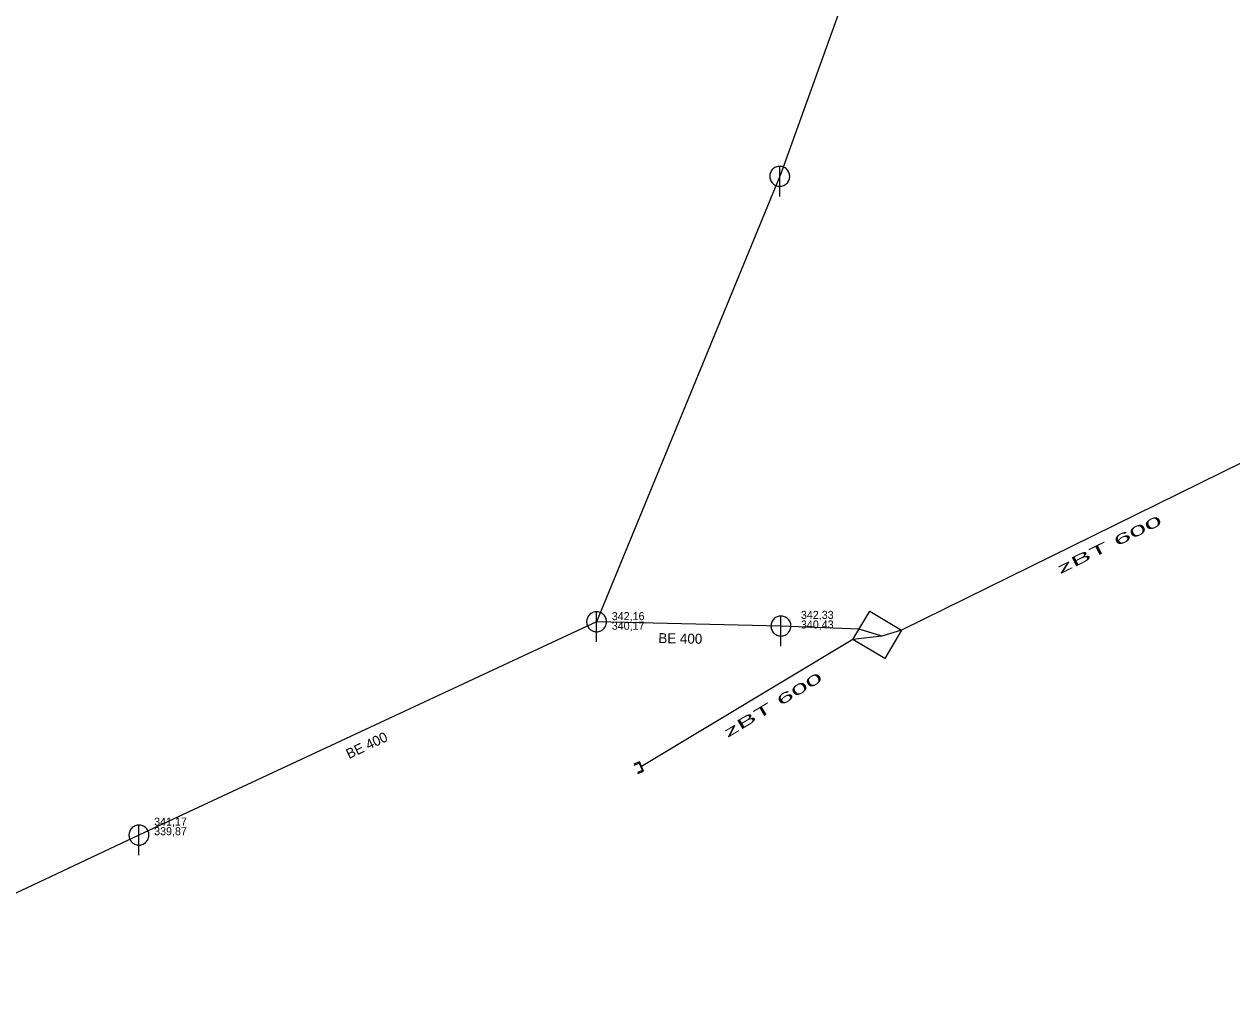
# Model space of a CAD drawing. Extents: x -724325 to -723665, y -972119 to -970722.
# Drawn here: x -724126.1 to -724005.4, y -971021.9 to -970925.2 of the extents above; entities that cross this region are included whole.
import ezdxf

# ---------------------------------------------------------------- set-up
doc = ezdxf.new("R2010")
doc.units = 0
doc.header["$LTSCALE"] = 0.4
for name, color, linetype, lineweight in [('1', 7, 'Continuous', 25), ('14', 7, 'Continuous', 25), ('22', 7, 'Continuous', 13), ('29', 7, 'Continuous', 13)]:
    doc.layers.add(name, color=color, linetype=linetype, lineweight=lineweight)
doc.layers.add('19', color=7, linetype='Continuous')

msp = doc.modelspace()

# ---------------------------------------------------------------- linework, layer by layer
at = {"layer": '1', "lineweight": 13}
msp.add_lwpolyline([(-724043.239, -970986.71), (-724041.559, -970983.87), (-724038.379, -970985.76), (-724040.059, -970988.59)], close=True, dxfattribs=at)
at = {"layer": '14'}
for p, q in [((-724032.99, -970891.76), (-724050.565, -970940.422)), ((-724050.565, -970940.421), (-724068.879, -970984.93)), ((-724114.64, -971006.25), (-724147.899, -971021.91))]:
    msp.add_line(p, q, dxfattribs=at)
for points in [[(-724002.16, -970967.949), (-724038.379, -970985.76), (-724040.368, -970986.355)], [(-724050.44, -970985.359), (-724068.879, -970984.93), (-724114.64, -971006.25)], [(-724040.368, -970986.355), (-724042.629, -970985.68), (-724050.44, -970985.359)], [(-724040.368, -970986.355), (-724043.239, -970986.71), (-724064.379, -970999.39)]]:
    msp.add_lwpolyline(points, dxfattribs=at)
at = {"layer": '22'}
for p, q in [((-724050.565, -970942.421), (-724050.564, -970939.421)), ((-724068.879, -970986.93), (-724068.878, -970983.93)), ((-724050.44, -970987.359), (-724050.439, -970984.359)), ((-724114.64, -971008.25), (-724114.639, -971005.25))]:
    msp.add_line(p, q, dxfattribs=at)
for points in [[(-724049.565, -970940.421), (-724049.57, -970940.312), (-724049.588, -970940.204), (-724049.618, -970940.098), (-724049.658, -970939.997), (-724049.71, -970939.9), (-724049.772, -970939.81), (-724049.844, -970939.727), (-724049.924, -970939.653), (-724050.012, -970939.587), (-724050.106, -970939.532), (-724050.206, -970939.487), (-724050.311, -970939.454), (-724050.418, -970939.432), (-724050.527, -970939.422), (-724050.637, -970939.424), (-724050.745, -970939.438), (-724050.852, -970939.463), (-724050.955, -970939.5), (-724051.053, -970939.549), (-724051.145, -970939.607), (-724051.231, -970939.676), (-724051.308, -970939.753), (-724051.377, -970939.839), (-724051.436, -970939.931), (-724051.484, -970940.029), (-724051.521, -970940.132), (-724051.547, -970940.239), (-724051.561, -970940.347), (-724051.564, -970940.457), (-724051.554, -970940.566), (-724051.533, -970940.673), (-724051.499, -970940.777), (-724051.455, -970940.877), (-724051.4, -970940.972), (-724051.334, -970941.06), (-724051.26, -970941.14), (-724051.177, -970941.212), (-724051.087, -970941.274), (-724050.991, -970941.326), (-724050.889, -970941.367), (-724050.784, -970941.397), (-724050.676, -970941.415), (-724050.566, -970941.421), (-724050.457, -970941.415), (-724050.349, -970941.397), (-724050.244, -970941.368), (-724050.142, -970941.327), (-724050.045, -970941.275), (-724049.955, -970941.213), (-724049.872, -970941.142), (-724049.797, -970941.062), (-724049.732, -970940.974), (-724049.676, -970940.88), (-724049.632, -970940.78), (-724049.598, -970940.676), (-724049.576, -970940.568), (-724049.566, -970940.459)], [(-724067.879, -970984.93), (-724067.884, -970984.821), (-724067.902, -970984.713), (-724067.932, -970984.607), (-724067.972, -970984.506), (-724068.024, -970984.409), (-724068.086, -970984.319), (-724068.158, -970984.236), (-724068.238, -970984.162), (-724068.326, -970984.096), (-724068.42, -970984.041), (-724068.52, -970983.996), (-724068.625, -970983.963), (-724068.732, -970983.941), (-724068.841, -970983.931), (-724068.951, -970983.933), (-724069.059, -970983.947), (-724069.166, -970983.972), (-724069.269, -970984.009), (-724069.367, -970984.058), (-724069.459, -970984.116), (-724069.545, -970984.185), (-724069.622, -970984.262), (-724069.691, -970984.348), (-724069.75, -970984.44), (-724069.798, -970984.538), (-724069.835, -970984.641), (-724069.861, -970984.748), (-724069.875, -970984.856), (-724069.878, -970984.966), (-724069.868, -970985.075), (-724069.847, -970985.182), (-724069.813, -970985.286), (-724069.769, -970985.386), (-724069.714, -970985.481), (-724069.648, -970985.569), (-724069.574, -970985.649), (-724069.491, -970985.721), (-724069.401, -970985.783), (-724069.305, -970985.835), (-724069.203, -970985.876), (-724069.098, -970985.906), (-724068.99, -970985.924), (-724068.88, -970985.93), (-724068.771, -970985.924), (-724068.663, -970985.906), (-724068.558, -970985.877), (-724068.456, -970985.836), (-724068.359, -970985.784), (-724068.269, -970985.722), (-724068.186, -970985.651), (-724068.111, -970985.571), (-724068.046, -970985.483), (-724067.99, -970985.389), (-724067.946, -970985.289), (-724067.912, -970985.185), (-724067.89, -970985.077), (-724067.88, -970984.968)], [(-724049.44, -970985.359), (-724049.445, -970985.25), (-724049.463, -970985.142), (-724049.493, -970985.036), (-724049.533, -970984.935), (-724049.585, -970984.838), (-724049.647, -970984.748), (-724049.719, -970984.665), (-724049.799, -970984.591), (-724049.887, -970984.525), (-724049.981, -970984.47), (-724050.081, -970984.425), (-724050.186, -970984.392), (-724050.293, -970984.37), (-724050.402, -970984.36), (-724050.512, -970984.362), (-724050.62, -970984.376), (-724050.727, -970984.401), (-724050.83, -970984.438), (-724050.928, -970984.487), (-724051.02, -970984.545), (-724051.106, -970984.614), (-724051.183, -970984.691), (-724051.252, -970984.777), (-724051.311, -970984.869), (-724051.359, -970984.967), (-724051.396, -970985.07), (-724051.422, -970985.177), (-724051.436, -970985.285), (-724051.439, -970985.395), (-724051.429, -970985.504), (-724051.408, -970985.611), (-724051.374, -970985.715), (-724051.33, -970985.815), (-724051.275, -970985.91), (-724051.209, -970985.998), (-724051.135, -970986.078), (-724051.052, -970986.15), (-724050.962, -970986.212), (-724050.866, -970986.264), (-724050.764, -970986.305), (-724050.659, -970986.335), (-724050.551, -970986.353), (-724050.441, -970986.359), (-724050.332, -970986.353), (-724050.224, -970986.335), (-724050.119, -970986.306), (-724050.017, -970986.265), (-724049.92, -970986.213), (-724049.83, -970986.151), (-724049.747, -970986.08), (-724049.672, -970986), (-724049.607, -970985.912), (-724049.551, -970985.818), (-724049.507, -970985.718), (-724049.473, -970985.614), (-724049.451, -970985.506), (-724049.441, -970985.397)], [(-724113.64, -971006.25), (-724113.645, -971006.141), (-724113.663, -971006.033), (-724113.693, -971005.927), (-724113.733, -971005.826), (-724113.785, -971005.729), (-724113.847, -971005.639), (-724113.919, -971005.556), (-724113.999, -971005.482), (-724114.087, -971005.416), (-724114.181, -971005.361), (-724114.281, -971005.316), (-724114.386, -971005.283), (-724114.493, -971005.261), (-724114.602, -971005.251), (-724114.712, -971005.253), (-724114.82, -971005.267), (-724114.927, -971005.292), (-724115.03, -971005.329), (-724115.128, -971005.378), (-724115.22, -971005.436), (-724115.306, -971005.505), (-724115.383, -971005.582), (-724115.452, -971005.668), (-724115.511, -971005.76), (-724115.559, -971005.858), (-724115.596, -971005.961), (-724115.622, -971006.068), (-724115.636, -971006.176), (-724115.639, -971006.286), (-724115.629, -971006.395), (-724115.608, -971006.502), (-724115.574, -971006.606), (-724115.53, -971006.706), (-724115.475, -971006.801), (-724115.409, -971006.889), (-724115.335, -971006.969), (-724115.252, -971007.041), (-724115.162, -971007.103), (-724115.066, -971007.155), (-724114.964, -971007.196), (-724114.859, -971007.226), (-724114.751, -971007.244), (-724114.641, -971007.25), (-724114.532, -971007.244), (-724114.424, -971007.226), (-724114.319, -971007.197), (-724114.217, -971007.156), (-724114.12, -971007.104), (-724114.03, -971007.042), (-724113.947, -971006.971), (-724113.872, -971006.891), (-724113.807, -971006.803), (-724113.751, -971006.709), (-724113.707, -971006.609), (-724113.673, -971006.505), (-724113.651, -971006.397), (-724113.641, -971006.288)]]:
    msp.add_lwpolyline(points, close=True, dxfattribs=at)
at = {"layer": '29'}
for points in [[(-724064.761, -971000.087), (-724064.188, -970999.848), (-724064.57, -970998.932), (-724065.144, -970999.172)], [(-724065.11, -970999.252), (-724064.617, -970999.045), (-724064.302, -970999.8), (-724064.796, -971000.006)]]:
    msp.add_lwpolyline(points, dxfattribs=at)

# ---------------------------------------------------------------- texts
at = {"layer": '1'}
for rotation, width, p in [(26, 2.3, (-724022.534, -970980.18)), (31, 2.25, (-724055.79, -970996.552))]:
    msp.add_text('zBT 600 ', height=1, rotation=rotation, dxfattribs=dict(at, width=width)).set_placement(p)
for rotation, p in [(359, (-724062.704, -970987.058)), (25, (-724093.64, -970998.656))]:
    msp.add_text('BE 400', height=1, rotation=rotation, dxfattribs=at).set_placement(p)
at = {"layer": '19'}
for s, p in [('342,16', (-724067.358, -970984.769)), ('340,17', (-724067.358, -970985.729)), ('342,33', (-724048.443, -970984.641)), ('340,43', (-724048.443, -970985.601)), ('341,17', (-724113.118, -971005.301)), ('339,87', (-724113.118, -971006.261))]:
    msp.add_text(s, height=0.8, dxfattribs=at).set_placement(p)

doc.saveas('drawing.dxf')
